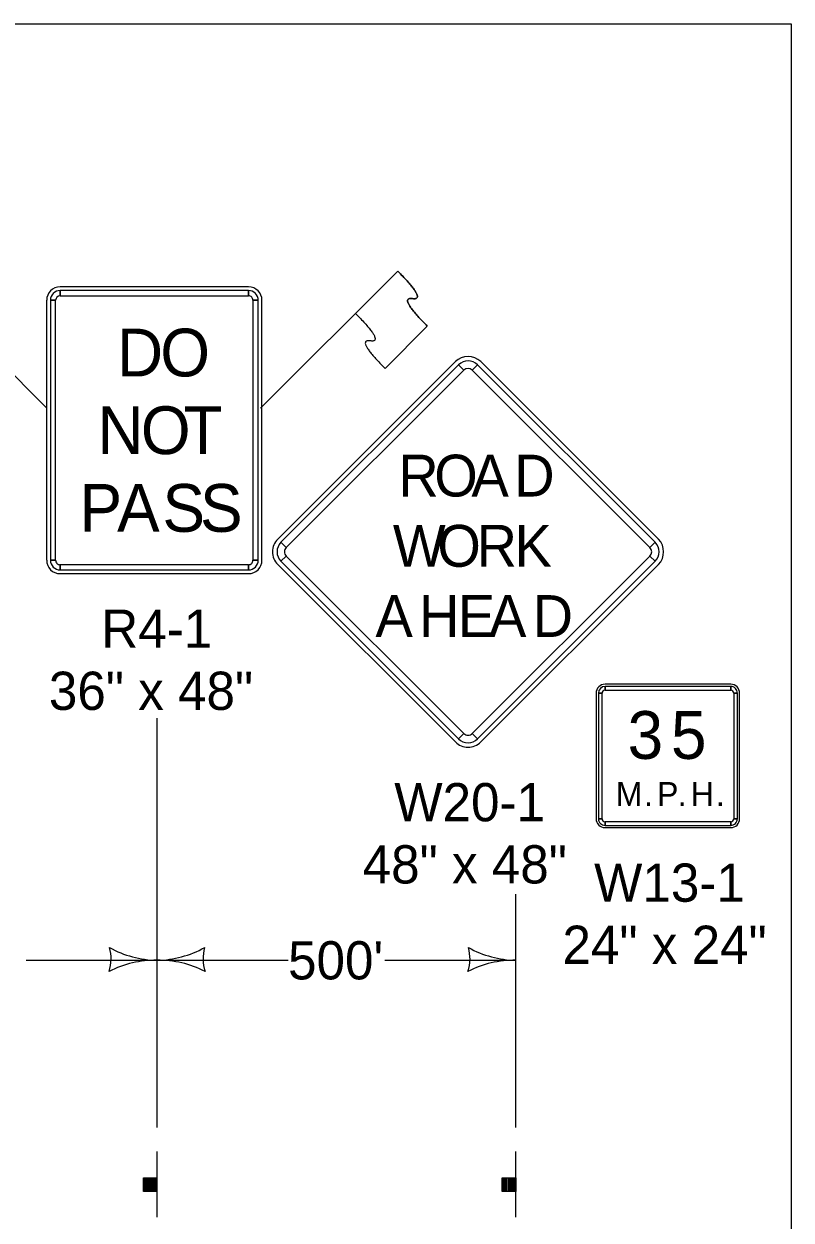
# Model space of a CAD drawing. Extents: x -2134934 to -2119606, y -2139046 to -2137036.
# Drawn here: x -2132120 to -2131799, y -2137536 to -2137036 of the extents above; entities that cross this region are included whole.
import ezdxf

# ---------------------------------------------------------------- set-up
doc = ezdxf.new("R2010")
doc.units = 0
for name, color, linetype in [('Default', 7, 'Continuous'), ('dsnStdLabel', 7, 'Continuous'), ('Level 2', 7, 'Continuous'), ('Level 5', 7, 'Continuous')]:
    doc.layers.add(name, color=color, linetype=linetype)

msp = doc.modelspace()

# ---------------------------------------------------------------- linework, layer by layer
at = {"layer": 'Default'}
msp.add_lwpolyline([(-2134934.44, -2137035.95), (-2131799.45, -2137035.95), (-2131799.45, -2139045.94), (-2134934.44, -2139045.94)], close=True, dxfattribs=at)
at = {"layer": 'dsnStdLabel'}
for p, q in [((-2132110.46, -2137196.68), (-2132167.8, -2137139.38)), ((-2132021.17, -2137196.68), (-2131963.85, -2137139.36)), ((-2131963.85, -2137139.36), (-2131981.54, -2137157.04)), ((-2132026.22, -2137145.92), (-2132104.97, -2137145.92)), ((-2132104.97, -2137149.67), (-2132104.97, -2137147.48)), ((-2132026.22, -2137147.48), (-2132026.22, -2137149.67)), ((-2132110.6, -2137151.54), (-2132110.6, -2137260.29)), ((-2132109.04, -2137151.54), (-2132106.85, -2137151.54)), ((-2132024.35, -2137151.54), (-2132022.16, -2137151.54)), ((-2132020.6, -2137260.29), (-2132020.6, -2137151.54)), ((-2131969.15, -2137180.03), (-2131951.48, -2137162.35)), ((-2131939.75, -2137177.23), (-2132014, -2137251.47)), ((-2131938.42, -2137178.55), (-2131936.21, -2137180.76)), ((-2131932.68, -2137180.76), (-2131930.47, -2137178.55)), ((-2131854.9, -2137251.47), (-2131929.14, -2137177.23)), ((-2132010.46, -2137255.01), (-2132012.67, -2137252.8)), ((-2131856.22, -2137252.8), (-2131858.43, -2137255.01)), ((-2132106.85, -2137260.29), (-2132109.04, -2137260.29)), ((-2132022.16, -2137260.29), (-2132024.35, -2137260.29)), ((-2132012.67, -2137260.75), (-2132010.46, -2137258.54)), ((-2131858.43, -2137258.54), (-2131856.22, -2137260.75)), ((-2132104.97, -2137264.35), (-2132104.97, -2137262.17)), ((-2132104.97, -2137265.92), (-2132026.22, -2137265.92)), ((-2132026.22, -2137262.17), (-2132026.22, -2137264.35)), ((-2132014, -2137262.08), (-2131939.75, -2137336.33)), ((-2131929.14, -2137336.33), (-2131854.9, -2137262.08)), ((-2131880.93, -2137315.92), (-2131880.93, -2137368.42)), ((-2131879.99, -2137315.92), (-2131878.43, -2137315.92)), ((-2131824.68, -2137312.17), (-2131877.18, -2137312.17)), ((-2131877.18, -2137314.67), (-2131877.18, -2137313.1)), ((-2131824.68, -2137313.1), (-2131824.68, -2137314.67)), ((-2131823.43, -2137315.92), (-2131821.86, -2137315.92)), ((-2131820.93, -2137368.42), (-2131820.93, -2137315.92)), ((-2131936.21, -2137332.79), (-2131938.42, -2137335)), ((-2131930.47, -2137335), (-2131932.68, -2137332.79)), ((-2131878.43, -2137368.42), (-2131879.99, -2137368.42)), ((-2131877.18, -2137371.23), (-2131877.18, -2137369.67)), ((-2131824.68, -2137369.67), (-2131824.68, -2137371.23)), ((-2131821.86, -2137368.42), (-2131823.43, -2137368.42)), ((-2131877.18, -2137372.17), (-2131824.68, -2137372.17))]:
    msp.add_line(p, q, dxfattribs=at)
for points in [[(-2132026.22, -2137147.48), (-2132104.97, -2137147.48), (-2132104.97, -2137149.67), (-2132026.22, -2137149.67), (-2132026.22, -2137147.48)], [(-2132109.04, -2137151.54), (-2132109.04, -2137260.29), (-2132106.85, -2137260.29), (-2132106.85, -2137151.54), (-2132109.04, -2137151.54)], [(-2132022.16, -2137260.29), (-2132022.16, -2137151.54), (-2132024.35, -2137151.54), (-2132024.35, -2137260.29), (-2132022.16, -2137260.29)], [(-2131938.42, -2137178.55), (-2132012.67, -2137252.8), (-2132010.46, -2137255.01), (-2131936.21, -2137180.76), (-2131938.42, -2137178.55)], [(-2131856.22, -2137252.8), (-2131930.47, -2137178.55), (-2131932.68, -2137180.76), (-2131858.43, -2137255.01), (-2131856.22, -2137252.8)], [(-2132012.67, -2137260.75), (-2131938.42, -2137335), (-2131936.21, -2137332.79), (-2132010.46, -2137258.54), (-2132012.67, -2137260.75)], [(-2131930.47, -2137335), (-2131856.22, -2137260.75), (-2131858.43, -2137258.54), (-2131932.68, -2137332.79), (-2131930.47, -2137335)], [(-2132104.97, -2137264.35), (-2132026.22, -2137264.35), (-2132026.22, -2137262.17), (-2132104.97, -2137262.17), (-2132104.97, -2137264.35)], [(-2131879.99, -2137315.92), (-2131879.99, -2137368.42), (-2131878.43, -2137368.42), (-2131878.43, -2137315.92), (-2131879.99, -2137315.92)], [(-2131824.68, -2137313.1), (-2131877.18, -2137313.1), (-2131877.18, -2137314.67), (-2131824.68, -2137314.67), (-2131824.68, -2137313.1)], [(-2131821.86, -2137368.42), (-2131821.86, -2137315.92), (-2131823.43, -2137315.92), (-2131823.43, -2137368.42), (-2131821.86, -2137368.42)], [(-2131877.18, -2137371.23), (-2131824.68, -2137371.23), (-2131824.68, -2137369.67), (-2131877.18, -2137369.67), (-2131877.18, -2137371.23)]]:
    msp.add_lwpolyline(points, close=True, dxfattribs=at)
for centre, radius, start, end in [((-2132104.97, -2137151.54), 5.62, 90.0002, 179.9998), ((-2132026.22, -2137151.54), 5.62, 0, 90.0002), ((-2132104.97, -2137151.54), 4.06, 90.0002, 179.9998), ((-2132104.97, -2137151.54), 1.87, 90.0002, 179.9998), ((-2132026.22, -2137151.54), 4.06, 0, 90.0002), ((-2132026.22, -2137151.54), 1.87, 0, 90.0002), ((-2131934.45, -2137182.53), 7.5, 45, 134.9997), ((-2131934.45, -2137182.53), 5.62, 45, 134.9997), ((-2131934.45, -2137182.53), 2.5, 45, 134.9997), ((-2132008.69, -2137256.78), 7.5, 134.9997, 225), ((-2132008.69, -2137256.78), 5.62, 134.9997, 225), ((-2132008.69, -2137256.78), 2.5, 134.9997, 225), ((-2131860.2, -2137256.78), 2.5, 315.0002, 44.9998), ((-2131860.2, -2137256.78), 5.62, 315.0002, 44.9998), ((-2131860.2, -2137256.78), 7.5, 315.0002, 44.9998), ((-2132104.97, -2137260.29), 5.62, 179.9998, 270.0001), ((-2132104.97, -2137260.29), 4.06, 179.9998, 270.0001), ((-2132104.97, -2137260.29), 1.87, 179.9998, 270.0001), ((-2132026.22, -2137260.29), 5.62, 270.0001, 0.0003), ((-2132026.22, -2137260.29), 4.06, 270.0001, 0.0003), ((-2132026.22, -2137260.29), 1.87, 270.0001, 0.0003), ((-2131877.18, -2137315.92), 3.75, 90.0002, 179.9998), ((-2131877.18, -2137315.92), 2.81, 90.0002, 179.9998), ((-2131877.18, -2137315.92), 1.25, 90.0002, 179.9998), ((-2131824.68, -2137315.92), 3.75, 0, 90.0002), ((-2131824.68, -2137315.92), 2.81, 0, 90.0002), ((-2131824.68, -2137315.92), 1.25, 0, 90.0002), ((-2131934.45, -2137331.02), 7.5, 225, 315.0002), ((-2131934.45, -2137331.02), 5.62, 225, 315.0002), ((-2131934.45, -2137331.02), 2.5, 225, 315.0002), ((-2131877.18, -2137368.42), 3.75, 179.9998, 270.0001), ((-2131877.18, -2137368.42), 2.81, 179.9998, 270.0001), ((-2131877.18, -2137368.42), 1.25, 179.9998, 270.0001), ((-2131824.68, -2137368.42), 3.75, 270.0001, 0.0003), ((-2131824.68, -2137368.42), 2.81, 270.0001, 0.0003), ((-2131824.68, -2137368.42), 1.25, 270.0001, 0.0003)]:
    msp.add_arc(centre, radius, start, end, dxfattribs=at)
for points in [[(-2131951.48, -2137162.35), (-2131963.85, -2137149.98), (-2131951.48, -2137151.75), (-2131963.85, -2137139.36)], [(-2131981.54, -2137157.04), (-2131969.16, -2137169.43), (-2131981.53, -2137167.66), (-2131969.15, -2137180.03)]]:
    msp.add_open_spline(points, degree=2, dxfattribs=at)
at = {"layer": 'Level 2'}
for p, q in [((-2132064.45, -2137497.66), (-2132064.45, -2137326.42)), ((-2131914.45, -2137497.66), (-2131914.45, -2137399.97)), ((-2132119.2, -2137427.66), (-2132064.45, -2137427.66)), ((-2132064.45, -2137427.66), (-2132009.7, -2137427.66)), ((-2131969.2, -2137427.66), (-2131914.45, -2137427.66)), ((-2132064.45, -2137535.16), (-2132064.45, -2137507.66)), ((-2131914.45, -2137535.16), (-2131914.45, -2137507.66)), ((-2132069.77, -2137524.3), (-2132069.77, -2137518.71)), ((-2132069.45, -2137518.71), (-2132069.45, -2137524.3)), ((-2132069.23, -2137524.3), (-2132069.23, -2137518.71)), ((-2132068.91, -2137518.71), (-2132068.91, -2137524.3)), ((-2132068.69, -2137524.3), (-2132068.7, -2137518.71)), ((-2132068.27, -2137518.71), (-2132068.25, -2137524.3)), ((-2132068.05, -2137524.3), (-2132068.05, -2137518.71)), ((-2132067.62, -2137518.71), (-2132067.62, -2137524.3)), ((-2132067.24, -2137524.3), (-2132067.24, -2137518.71)), ((-2132066.92, -2137518.71), (-2132066.9, -2137524.3)), ((-2132066.7, -2137524.3), (-2132066.7, -2137518.71)), ((-2132066.43, -2137518.71), (-2132066.43, -2137524.3)), ((-2132066.1, -2137524.3), (-2132066.1, -2137518.71)), ((-2132065.89, -2137518.71), (-2132065.89, -2137524.3)), ((-2132065.67, -2137524.3), (-2132065.67, -2137518.71)), ((-2132065.4, -2137518.71), (-2132065.4, -2137524.3)), ((-2132065.14, -2137524.3), (-2132065.14, -2137518.71)), ((-2132064.86, -2137518.71), (-2132064.86, -2137524.3)), ((-2131919.77, -2137524.3), (-2131919.77, -2137518.71)), ((-2131919.45, -2137518.71), (-2131919.45, -2137524.3)), ((-2131919.23, -2137524.3), (-2131919.23, -2137518.71)), ((-2131918.91, -2137518.71), (-2131918.91, -2137524.3)), ((-2131918.69, -2137524.3), (-2131918.7, -2137518.71)), ((-2131918.27, -2137518.71), (-2131918.25, -2137524.3)), ((-2131918.05, -2137524.3), (-2131918.05, -2137518.71)), ((-2131917.62, -2137518.71), (-2131917.62, -2137524.3)), ((-2131917.24, -2137524.3), (-2131917.24, -2137518.71)), ((-2131916.92, -2137518.71), (-2131916.9, -2137524.3)), ((-2131916.7, -2137524.3), (-2131916.7, -2137518.71)), ((-2131916.43, -2137518.71), (-2131916.43, -2137524.3)), ((-2131916.1, -2137524.3), (-2131916.1, -2137518.71)), ((-2131915.89, -2137518.71), (-2131915.89, -2137524.3)), ((-2131915.67, -2137524.3), (-2131915.67, -2137518.71)), ((-2131915.4, -2137518.71), (-2131915.4, -2137524.3)), ((-2131915.14, -2137524.3), (-2131915.14, -2137518.71)), ((-2131914.86, -2137518.71), (-2131914.86, -2137524.3))]:
    msp.add_line(p, q, dxfattribs=at)
for points in [[(-2132064.54, -2137518.71), (-2132064.54, -2137524.34), (-2132070.17, -2137524.34), (-2132070.17, -2137518.71)], [(-2131914.54, -2137518.71), (-2131914.54, -2137524.34), (-2131920.17, -2137524.34), (-2131920.17, -2137518.71)]]:
    msp.add_lwpolyline(points, close=True, dxfattribs=at)
for centre, radius, start, end in [((-2132100.06, -2137427.04), 16.42, 341.2666, 16.7334), ((-2132063.69, -2137385.17), 42.5, 240.9275, 268.9824), ((-2132065.2, -2137385.17), 42.5, 271.0176, 299.0725), ((-2132028.83, -2137427.04), 16.42, 163.2666, 198.7334), ((-2131950.06, -2137427.04), 16.42, 341.2666, 16.7334), ((-2131913.69, -2137385.17), 42.5, 240.9275, 268.9824), ((-2132065.18, -2137470.15), 42.5, 89.0176, 117.0725), ((-2132063.72, -2137470.15), 42.5, 62.9275, 90.9824), ((-2131915.18, -2137470.15), 42.5, 89.0176, 117.0725)]:
    msp.add_arc(centre, radius, start, end, dxfattribs=at)
at = {"layer": 'Level 5'}
msp.add_line((-2131951.48, -2137162.35), (-2131969.15, -2137180.03), dxfattribs=at)
for points in [[(-2131963.85, -2137139.36), (-2131951.48, -2137151.75), (-2131963.85, -2137149.98), (-2131951.48, -2137162.35)], [(-2131981.54, -2137157.04), (-2131969.16, -2137169.43), (-2131981.53, -2137167.66), (-2131969.15, -2137180.03)]]:
    msp.add_open_spline(points, degree=2, dxfattribs=at)

# ---------------------------------------------------------------- texts
at = {"layer": 'dsnStdLabel'}
for s, height, p in [('D', 20, (-2132081.22, -2137183.42)), ('O', 20, (-2132063.1, -2137183.42)), ('N', 20, (-2132089.35, -2137215.92)), ('O', 20, (-2132071.22, -2137215.92)), ('T', 20, (-2132053.41, -2137215.92)), ('R', 17.5, (-2131963.61, -2137233.65)), ('O', 17.5, (-2131948.6, -2137233.65)), ('A', 17.5, (-2131933.05, -2137233.65)), ('D', 17.5, (-2131915.17, -2137233.65)), ('P', 20, (-2132096.86, -2137248.42)), ('A', 20, (-2132081.18, -2137248.42)), ('S', 20, (-2132062.21, -2137248.42)), ('S', 20, (-2132046.52, -2137248.42)), ('W', 17.5, (-2131965.89, -2137263.03)), ('O', 17.5, (-2131947.3, -2137263.03)), ('R', 17.5, (-2131930.89, -2137263.03)), ('K', 17.5, (-2131915.03, -2137263.03)), ('A', 17.5, (-2131973.17, -2137292.4)), ('H', 17.5, (-2131954.96, -2137292.4)), ('E', 17.5, (-2131938.73, -2137292.4)), ('A', 17.5, (-2131925.69, -2137292.4)), ('D', 17.5, (-2131907.48, -2137292.4)), ('R4-1', 16, (-2132087.76, -2137296.92)), ('36" x 48"', 16, (-2132109.67, -2137322.92)), ('3', 20, (-2131867.78, -2137343.41)), ('5', 20, (-2131849.65, -2137343.41)), ('W20-1', 16, (-2131965.3, -2137369.52)), ('M', 10, (-2131872.7, -2137363.1)), ('P', 10, (-2131855.45, -2137363.1)), ('H', 10, (-2131841.33, -2137363.1)), ('.', 10, (-2131860.91, -2137363.1)), ('.', 10, (-2131846.79, -2137363.1)), ('.', 10, (-2131830.86, -2137363.1)), ('48" x 48"', 16, (-2131978.51, -2137395.52)), ('W13-1', 16, (-2131881.78, -2137403.17)), ('24" x 24"', 16, (-2131894.99, -2137429.17))]:
    msp.add_text(s, height=height, dxfattribs=at).set_placement(p)
at = {"layer": 'Level 2'}
msp.add_text("500'", height=16, dxfattribs=at).set_placement((-2132009.7, -2137435.66))

doc.saveas('drawing.dxf')
